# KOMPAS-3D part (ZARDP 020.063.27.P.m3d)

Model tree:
1. Плоскость XY
2. Плоскость ZX
3. Плоскость ZY
4. Ось X
5. Ось Y
6. Ось Z
7. Начало координат
8. Булева операция:1
9. Булева операция:2
10. Булева операция:3
11. Булева операция:4
